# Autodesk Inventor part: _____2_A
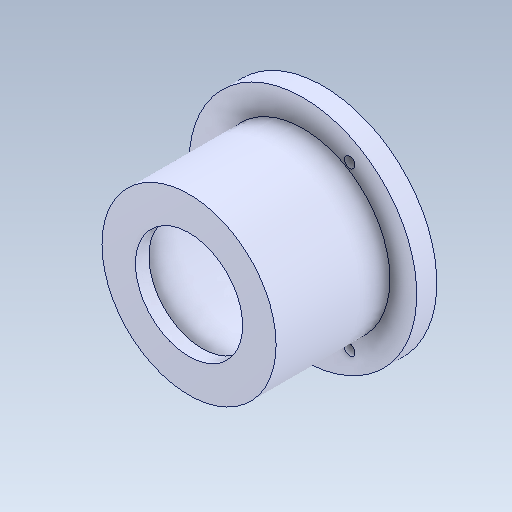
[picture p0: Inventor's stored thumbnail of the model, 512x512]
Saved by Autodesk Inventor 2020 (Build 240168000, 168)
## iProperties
Created: 2017-09
Part Number: _____2_A
Material: Générique
Document SubType Name: Modeling
Designer: bruno
Density: 1 g/cm^3
Appearance: Par défaut
Mass: 4.48695 g
Surface Area: 45.0052 cm^2
Volume: 4.48695 cm^3
Sending System: SolidWorks 2016
Author: bruno
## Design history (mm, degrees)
feature "Importée1"
node "Solide1"
